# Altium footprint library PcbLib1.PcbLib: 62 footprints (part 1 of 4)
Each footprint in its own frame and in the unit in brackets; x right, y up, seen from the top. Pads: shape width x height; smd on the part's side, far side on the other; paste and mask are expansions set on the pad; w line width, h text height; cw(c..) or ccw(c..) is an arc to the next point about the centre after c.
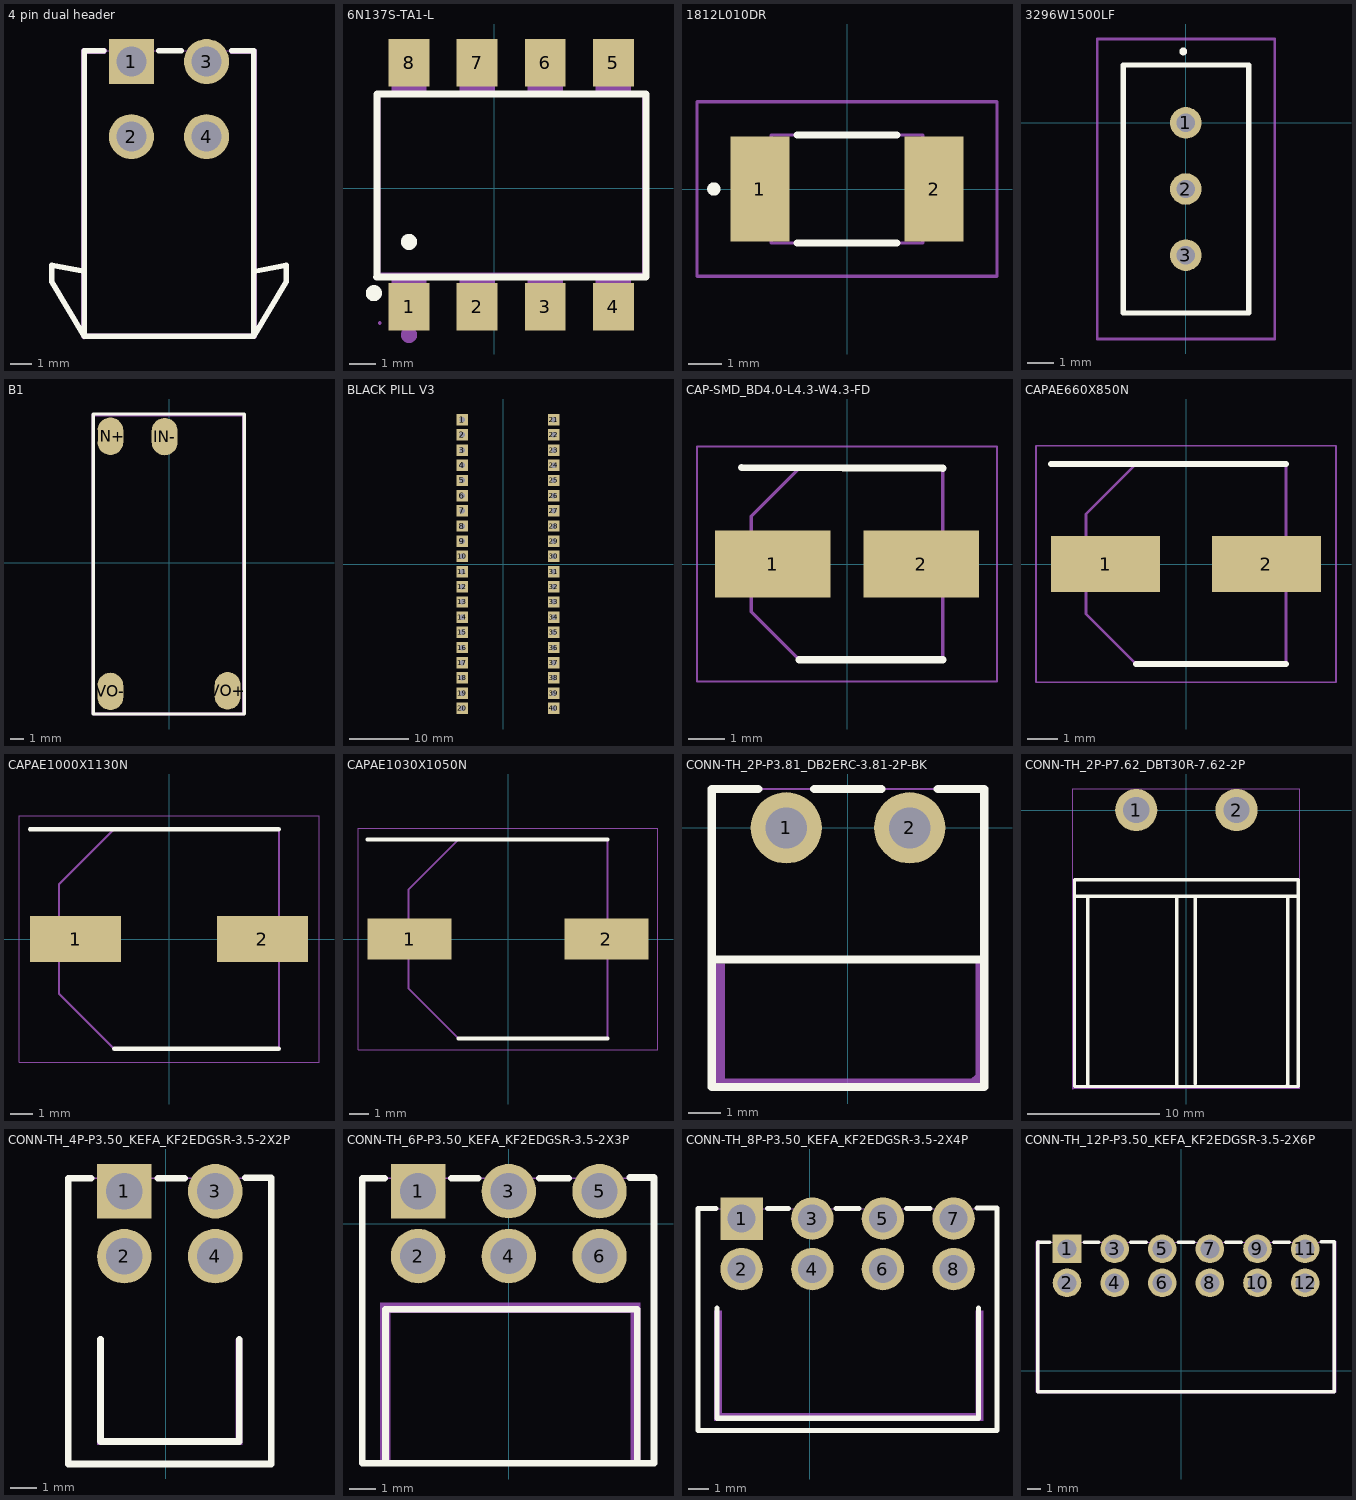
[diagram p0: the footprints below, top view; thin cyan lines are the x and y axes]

## 4 pin dual header [mm]
pads (4):
  rect 2.1x2.1 hole 1.4 paste-2539.97 mask+0.05: 1(12.728,17.118)
  round 2.1 hole 1.4 paste-2539.97 mask+0.05: 2(12.728,13.618) 3(16.228,17.118) 4(16.228,13.618)
Top Overlay:
  lines w0.254: 10.528,4.319 9.017,6.859 9.017,7.621 10.528,7.352 ; 11.447,17.618 10.528,17.618 10.528,4.318 18.428,4.318 18.428,17.527 ; 14.009,17.618 15.049,17.618 ; 17.407,17.618 18.428,17.618 ; 18.428,4.319 19.939,6.859 19.939,7.621 18.428,7.336
Mechanical 6:
  region: 11.447,17.491 10.655,17.491 10.655,4.445 18.301,4.445 18.301,17.527 18.301,17.58 18.375,17.654 18.481,17.654 18.555,17.58 18.555,17.527 18.555,4.318 18.555,4.293 18.536,4.246 18.5,4.21 18.453,4.191 18.428,4.191 10.528,4.191 10.503,4.191 10.456,4.21 10.42,4.246 10.401,4.293 10.401,4.318 10.401,17.618 10.401,17.643 10.42,17.69 10.456,17.726 10.503,17.745 10.528,17.745 11.447,17.745 11.499,17.745 11.574,17.671 11.574,17.565 11.499,17.491
  region: 17.407,17.745 18.428,17.745 18.481,17.745 18.555,17.671 18.555,17.565 18.481,17.491 18.428,17.491 17.407,17.491 17.355,17.491 17.28,17.565 17.28,17.671 17.355,17.745
Mechanical 15:
  region: 10.588,17.618 10.587,17.642 10.552,17.676 10.504,17.676 10.469,17.642 10.468,17.618 10.469,17.594 10.504,17.56 10.552,17.56 10.587,17.594
  region: 12.328,17.518 13.128,17.518 13.128,16.718 12.328,16.718
  region: 12.328,14.018 13.128,14.018 13.128,13.218 12.328,13.218
  region: 15.828,17.518 16.628,17.518 16.628,16.718 15.828,16.718
  region: 15.828,14.018 16.628,14.018 16.628,13.218 15.828,13.218
  lines w0.051: 10.528,4.318 10.528,17.618 18.428,17.618 18.428,4.318 10.528,4.318

## 6N137S-TA1-L [mm]
pads (8):
  rect 1.525x1.78 smd: 1(-3.175,-4.418) 2(-0.635,-4.418) 3(1.905,-4.418) 4(4.445,-4.418) 5(4.445,4.672) 6(1.905,4.672) 7(-0.635,4.672) 8(-3.175,4.672)
Top Overlay:
  circle w0.3: c-3.175,-2.002 r0.15
  circle w0.3: c-4.485,-3.913 r0.15
  lines w0.254: -4.385,-3.313 5.665,-3.313 5.665,3.517 4.925,3.517 -4.365,3.517 -4.375,-3.293
Mechanical 6:
  circle w0.3: c-3.175,-5.473 r0.15
Mechanical 15:
  region: -4.205,-5.023 -4.205,-4.998 -4.24,-4.963 -4.29,-4.963 -4.325,-4.998 -4.325,-5.023 -4.325,-5.048 -4.29,-5.083 -4.24,-5.083 -4.205,-5.048
  region: 3.795,3.417 3.795,4.337 5.095,4.337 5.095,3.417
  region: 3.795,4.327 3.795,5.277 5.095,5.277 5.095,4.327
  region: 1.255,3.417 1.255,4.337 2.555,4.337 2.555,3.417
  region: 1.255,4.327 1.255,5.277 2.555,5.277 2.555,4.327
  region: -1.285,3.417 -1.285,4.337 0.015,4.337 0.015,3.417
  region: -1.285,4.327 -1.285,5.277 0.015,5.277 0.015,4.327
  region: -3.825,3.417 -3.825,4.337 -2.525,4.337 -2.525,3.417
  region: -3.825,4.327 -3.825,5.277 -2.525,5.277 -2.525,4.327
  region: 3.795,-4.083 3.795,-3.163 5.095,-3.163 5.095,-4.083
  region: 3.795,-5.023 3.795,-4.073 5.095,-4.073 5.095,-5.023
  region: 1.255,-4.083 1.255,-3.163 2.555,-3.163 2.555,-4.083
  region: 1.255,-5.023 1.255,-4.073 2.555,-4.073 2.555,-5.023
  region: -1.285,-4.083 -1.285,-3.163 0.015,-3.163 0.015,-4.083
  region: -1.285,-5.023 -1.285,-4.073 0.015,-4.073 0.015,-5.023
  region: -3.825,-4.083 -3.825,-3.163 -2.525,-3.163 -2.525,-4.083
  region: -3.825,-5.023 -3.825,-4.073 -2.525,-4.073 -2.525,-5.023
  lines w0.051: -4.265,-3.173 -4.265,3.427 5.535,3.427 5.535,-3.173 -4.265,-3.173
3D body "6N137S-TA1-L.STEP": height 4.61, standoff 0.01, extent -4.205,-5.08 5.475,5.08

## 1812L010DR [mm]
pads (2):
  rect 1.78x3.15 smd: 1(-2.615,0) 2(2.615,0)
Top Overlay:
  lines w0.2: -1.5,-1.62 1.5,-1.62 ; -1.5,1.62 1.5,1.62 ; -4,-0.1 ccw(c-4,0) -4,0.1 ccw(c-4,0) -4,-0.1
Mechanical 13:
  lines w0.1: -2.275,-1.62 -2.275,1.62 2.275,1.62 2.275,-1.62 -2.275,-1.62
Mechanical 15:
  lines w0.1: -4.505,-2.62 -4.505,2.62 4.505,2.62 4.505,-2.62 -4.505,-2.62
3D body "1812L200THPR.stp": height 0.75, standoff 0, extent -2.277,-1.625 2.277,1.625

## 3296W1500LF [mm]
pads (3):
  round 1.217 hole 0.71: 1(0,0) 2(0,-2.54) 3(0,-5.08)
Top Overlay:
  lines w0.2: -0.1,2.7 cw(c-0.1,2.75) -0.1,2.8 ; -0.1,2.7 ccw(c-0.1,2.75) -0.1,2.8 ; -0.1,2.7 cw(c-0.1,2.75) -0.1,2.8 ; -2.41,-7.305 -2.41,2.225 2.42,2.225 2.42,-7.305 -2.41,-7.305
Mechanical 13:
  lines w0.1: -2.41,-7.305 -2.41,2.225 2.42,2.225 2.42,-7.305 -2.41,-7.305
Mechanical 15:
  lines w0.1: -3.41,-8.305 -3.41,3.225 3.42,3.225 3.42,-8.305 -3.41,-8.305
3D body "3296W-1-500LF.stp": height 11.9, standoff -5, extent -2.41,-7.305 2.42,2.225

## B1 [mm]
pads (4):
  oval 1.9x2.75 smd: IN+(-4.319,9.288) IN-(-0.336,9.264) VO+(4.284,-9.39) VO-(-4.323,-9.429)
Top Overlay:
  lines w0.254: -5.588,-11.087 5.488,-11.087 5.488,10.922 -5.588,10.922 -5.588,-11.087
Mechanical 1:
  lines w0.254: -5.587,-11.088 -5.587,10.87 5.469,10.87 5.469,-11.088 -5.587,-11.088
3D body "mini dc dc boost module.step": height 3.4, standoff -1, extent -5.459,-10.964 5.341,10.836

## BLACK PILL V3 [mil]
pads (40):
  rect 75x75 hole 36 paste-99999 mask+4: 1(-267.5,950) 2(-267.5,850) 3(-267.5,750) 4(-267.5,650) 5(-267.5,550) 6(-267.5,450) 7(-267.5,350) 8(-267.5,250) 9(-267.5,150) 10(-267.5,50) 11(-267.5,-50) 12(-267.5,-150) 13(-267.5,-250) 14(-267.5,-350) 15(-267.5,-450) 16(-267.5,-550) 17(-267.5,-650) 18(-267.5,-750) 19(-267.5,-850) 20(-267.5,-950) 21(332.5,950) 22(332.5,850) 23(332.5,750) 24(332.5,650) 25(332.5,550) 26(332.5,450) 27(332.5,350) 28(332.5,250) 29(332.5,150) 30(332.5,50) 31(332.5,-50) 32(332.5,-150) 33(332.5,-250) 34(332.5,-350) 35(332.5,-450) 36(332.5,-550) 37(332.5,-650) 38(332.5,-750) 39(332.5,-850) 40(332.5,-950)
3D body "Black Pill.step": height 124.41, standoff -403.94, extent -365,-1175 435,1054.92

## CAP-SMD_BD4.0-L4.3-W4.3-FD [mm]
pads (2):
  rect 3.2x1.85 smd: 1(-2.05,0) 2(2.05,0)
Top Overlay:
  lines w0.2: -2.921,2.667 2.65,2.65 ; -1.325,-2.65 2.65,-2.65
Mechanical 13:
  lines w0.1: -2.65,-1.325 -1.325,-2.65 2.65,-2.65 2.65,2.65 -1.325,2.65 -2.65,1.325 -2.65,-1.325
Mechanical 15:
  lines w0.05: -4.15,-3.25 -4.15,3.25 4.15,3.25 4.15,-3.25 -4.15,-3.25
3D body "UWT1E100MCL1GB.stp": height 5.5, standoff 0, extent -2.95,-2.75 2.95,2.75

## CAPAE660X850N [mm]
pads (2):
  rect 3.6x1.85 smd: 1(-2.65,0) 2(2.65,0)
Top Overlay:
  lines w0.2: -4.45,3.3 3.3,3.3 ; -1.65,-3.3 3.3,-3.3
Mechanical 13:
  lines w0.1: -3.3,-1.65 -3.3,1.65 -1.65,3.3 3.3,3.3 3.3,-3.3 -1.65,-3.3 -3.3,-1.65
Mechanical 15:
  lines w0.05: -4.95,-3.9 4.95,-3.9 4.95,3.9 -4.95,3.9 -4.95,-3.9
3D body "AEK0608100M100R.stp": height 8.5, standoff 0, extent -3.75,-3.4 3.75,3.4

## CAPAE1000X1130N [mm]
pads (2):
  rect 4.15x2.1 smd: 1(-4.25,0) 2(4.25,0)
Top Overlay:
  lines w0.2: -6.325,5 5,5 ; -2.5,-5 5,-5
Mechanical 13:
  lines w0.1: -5,-2.5 -5,2.5 -2.5,5 5,5 5,-5 -2.5,-5 -5,-2.5
Mechanical 15:
  lines w0.05: -6.825,-5.6 6.825,-5.6 6.825,5.6 -6.825,5.6 -6.825,-5.6
3D body "476SML100M.stp": height 11.3, standoff 0, extent -5.6,-5.1 5.6,5.1

## CAPAE1030X1050N [mm]
pads (2):
  rect 4.35x2.1 smd: 1(-5.1,0) 2(5.1,0)
Top Overlay:
  lines w0.2: -7.275,5.15 5.15,5.15 ; -2.575,-5.15 5.15,-5.15
Mechanical 13:
  lines w0.1: -5.15,-2.575 -5.15,2.575 -2.575,5.15 5.15,5.15 5.15,-5.15 -2.575,-5.15 -5.15,-2.575
Mechanical 15:
  lines w0.05: -7.775,-5.75 7.775,-5.75 7.775,5.75 -7.775,5.75 -7.775,-5.75
3D body "EDH476M100A9PAA.stp": height 10.51, standoff 0, extent -6.1,-5.25 6.1,5.25

## CONN-TH_2P-P3.81_DB2ERC-3.81-2P-BK [mm]
pads (2):
  round 2.2 hole 1.27: 1(-1.905,0) 2(1.905,0)
Top Overlay:
  lines w0.254: -4.205,-4.064 4.205,-4.064 ; -2.771,1.2 -4.205,1.2 -4.205,-8 4.205,-8 4.205,1.2 2.771,1.2 ; -1.039,1.2 1.039,1.2
Mechanical 6:
  region: 4.191,-4.064 4.191,-8.001 -4.191,-8.001 -4.191,-4.191 -3.81,-4.191 -3.81,-7.747 3.81,-7.747 3.937,-7.62 3.937,-4.064
Mechanical 15:
  region: -4.145,-8 -4.145,-8.025 -4.18,-8.06 -4.23,-8.06 -4.265,-8.025 -4.265,-8 -4.265,-7.975 -4.23,-7.94 -4.18,-7.94 -4.145,-7.975 -4.145,-8
  region: 1.505,0.4 2.305,0.4 2.305,-0.4 1.505,-0.4
  region: -2.305,0.4 -1.505,0.4 -1.505,-0.4 -2.305,-0.4
  lines w0.051: -4.205,-8 4.205,-8 4.205,1.2 -4.205,1.2 -4.205,-8

## CONN-TH_2P-P7.62_DBT30R-7.62-2P [mm]
pads (2):
  round 3.2 hole 2: 1(-3.81,0) 2(3.81,0)
Top Overlay:
  lines w0.254: -8.5,-6.554 8.5,-6.554 ; -7.486,-21 -7.486,-6.554 ; -0.735,-21 -0.735,-6.554 ; 0.668,-20.79 0.668,-6.554 ; 7.553,-21 7.687,-20.866 7.687,-20.86 7.687,-6.554 ; 8.5,-21 -8.5,-21 -8.5,-5.3 8.5,-5.3 8.5,-20.99
Mechanical 15:
  region: -2.91,0 -2.91,-0.118 -2.971,-0.347 -3.09,-0.553 -3.257,-0.72 -3.463,-0.839 -3.692,-0.9 -3.928,-0.9 -4.157,-0.839 -4.363,-0.72 -4.53,-0.553 -4.649,-0.347 -4.71,-0.118 -4.71,0 -4.71,0.118 -4.649,0.347 -4.53,0.553 -4.363,0.72 -4.157,0.839 -3.928,0.9 -3.692,0.9 -3.463,0.839 -3.257,0.72 -3.09,0.553 -2.971,0.347 -2.91,0.118
  region: 4.71,0 4.71,-0.118 4.649,-0.347 4.53,-0.553 4.363,-0.72 4.157,-0.839 3.928,-0.9 3.692,-0.9 3.463,-0.839 3.257,-0.72 3.09,-0.553 2.971,-0.347 2.91,-0.118 2.91,0 2.91,0.118 2.971,0.347 3.09,0.553 3.257,0.72 3.463,0.839 3.692,0.9 3.928,0.9 4.157,0.839 4.363,0.72 4.53,0.553 4.649,0.347 4.71,0.118
  region: -8.567,-21.127 -8.567,-21.152 -8.602,-21.187 -8.652,-21.187 -8.687,-21.152 -8.687,-21.127 -8.687,-21.102 -8.652,-21.067 -8.602,-21.067 -8.567,-21.102
  lines w0.051: -8.627,-21.127 8.627,-21.127 8.627,1.6 -8.627,1.6 -8.627,-21.127

## CONN-TH_4P-P3.50_KEFA_KF2EDGSR-3.5-2X2P [mm]
pads (4):
  rect 2.1x2.1 hole 1.4 paste-2539.97 mask+0.05: 1(-1.6,11.897)
  round 2.1 hole 1.4 paste-2539.97 mask+0.05: 2(-1.6,9.397) 3(1.9,11.897) 4(1.9,9.397)
Top Overlay:
  lines w0.254: -3.759,1.397 -3.759,12.397 -2.881,12.397 ; -3.75,1.397 4.05,1.397 4.05,12.425 3.067,12.425 ; -2.517,6.202 -2.517,2.265 2.817,2.265 2.817,6.202 ; -0.319,12.397 0.721,12.397
Mechanical 6:
  region: 2.69,6.202 2.69,2.392 -2.39,2.392 -2.39,6.202 -2.644,6.202 -2.644,2.138 2.817,2.138 2.944,2.138 2.944,6.202
Mechanical 15:
  region: -3.69,12.397 -3.69,12.372 -3.725,12.337 -3.775,12.337 -3.81,12.372 -3.81,12.397 -3.81,12.422 -3.775,12.457 -3.725,12.457 -3.69,12.422
  region: 1.5,9.797 2.3,9.797 2.3,8.997 1.5,8.997
  region: 1.5,12.297 2.3,12.297 2.3,11.497 1.5,11.497
  region: -2,9.797 -1.2,9.797 -1.2,8.997 -2,8.997
  region: -2,12.297 -1.2,12.297 -1.2,11.497 -2,11.497
  lines w0.051: -3.75,1.397 -3.75,12.397 4.05,12.397 4.05,1.397 -3.75,1.397

## CONN-TH_6P-P3.50_KEFA_KF2EDGSR-3.5-2X3P [mm]
pads (6):
  rect 2.1x2.1 hole 1.4 paste-2539.97 mask+0.05: 1(-3.5,1.25)
  round 2.1 hole 1.4 paste-2539.97 mask+0.05: 2(-3.5,-1.25) 3(0,1.25) 5(3.5,1.25) 6(3.5,-1.25)
  round 2.1 hole 1.4 copper offset 0,0 paste-2539.97 mask+0.05: 4(0,-1.25)
Top Overlay:
  lines w0.254: -5.659,-9.25 -5.659,1.75 -4.781,1.75 ; -5.65,-9.25 5.6,-9.25 5.6,1.778 4.667,1.778 ; -4.756,-9.25 -4.756,-3.302 4.953,-3.302 4.953,-9.25 ; -2.219,1.75 -1.179,1.75 ; 1.179,1.75 2.321,1.75
Mechanical 6:
  region: -4.953,-9.25 -4.953,-3.048 5.08,-3.048 5.08,-9.25 4.699,-9.25 4.699,-3.429 -4.572,-3.429 -4.572,-9.25 -4.699,-9.271
Mechanical 15:
  region: -5.59,1.75 -5.59,1.725 -5.625,1.69 -5.675,1.69 -5.71,1.725 -5.71,1.75 -5.71,1.775 -5.675,1.81 -5.625,1.81 -5.59,1.775
  region: 3.1,-0.85 3.9,-0.85 3.9,-1.65 3.1,-1.65
  region: 3.1,1.65 3.9,1.65 3.9,0.85 3.1,0.85
  region: -3.9,1.65 -3.1,1.65 -3.1,0.85 -3.9,0.85
  region: -3.9,-0.85 -3.1,-0.85 -3.1,-1.65 -3.9,-1.65
  region: -0.4,1.65 0.4,1.65 0.4,0.85 -0.4,0.85
  region: -0.4,-0.85 0.4,-0.85 0.4,-1.65 -0.4,-1.65
  lines w0.051: -5.65,-9.25 -5.65,1.75 5.65,1.75 5.65,-9.25 -5.65,-9.25

## CONN-TH_8P-P3.50_KEFA_KF2EDGSR-3.5-2X4P [mm]
pads (8):
  rect 2.1x2.1 hole 1.4 paste-2539.97 mask+0.05: 1(-3.378,16.088)
  round 2.1 hole 1.4 paste-2539.97 mask+0.05: 2(-3.378,13.588) 3(0.122,16.088) 5(3.622,16.088) 6(3.622,13.588) 7(7.122,16.088) 8(7.122,13.588)
  round 2.1 hole 1.4 copper offset 0,0 paste-2539.97 mask+0.05: 4(0.122,13.588)
Top Overlay:
  lines w0.254: -5.537,5.588 -5.537,16.588 -4.659,16.588 ; -5.528,5.588 9.272,5.588 9.272,16.616 8.289,16.616 ; -4.605,11.663 -4.605,6.202 8.349,6.202 8.349,11.663 ; -2.097,16.588 -1.057,16.588 ; 1.301,16.588 2.443,16.588 ; 4.801,16.588 5.943,16.588
Mechanical 6:
  region: 8.222,11.536 8.222,6.456 -4.351,6.456 -4.351,11.536 -4.732,11.536 -4.732,6.075 8.603,6.075 8.603,11.536
Mechanical 15:
  region: -5.468,16.588 -5.468,16.563 -5.503,16.528 -5.553,16.528 -5.588,16.563 -5.588,16.588 -5.588,16.613 -5.553,16.648 -5.503,16.648 -5.468,16.613
  region: 6.722,13.988 7.522,13.988 7.522,13.188 6.722,13.188
  region: 6.722,16.488 7.522,16.488 7.522,15.688 6.722,15.688
  region: 3.222,13.988 4.022,13.988 4.022,13.188 3.222,13.188
  region: 3.222,16.488 4.022,16.488 4.022,15.688 3.222,15.688
  region: -3.778,16.488 -2.978,16.488 -2.978,15.688 -3.778,15.688
  region: -3.778,13.988 -2.978,13.988 -2.978,13.188 -3.778,13.188
  region: -0.278,16.488 0.522,16.488 0.522,15.688 -0.278,15.688
  region: -0.278,13.988 0.522,13.988 0.522,13.188 -0.278,13.188
  lines w0.051: -5.528,5.588 -5.528,16.588 9.272,16.588 9.272,5.588 -5.528,5.588

## CONN-TH_12P-P3.50_KEFA_KF2EDGSR-3.5-2X6P [mm]
pads (12):
  rect 2.1x2.1 hole 1.4 paste-2539.97 mask+0.05: 1(-8.388,8.969)
  round 2.1 hole 1.4 paste-2539.97 mask+0.05: 2(-8.388,6.469) 3(-4.888,8.969) 5(-1.388,8.969) 6(-1.388,6.469) 7(2.112,8.969) 8(2.112,6.469) 9(5.612,8.969) 10(5.612,6.469) 11(9.112,8.969) 12(9.112,6.469)
  round 2.1 hole 1.4 copper offset 0,0 paste-2539.97 mask+0.05: 4(-4.888,6.469)
Top Overlay:
  lines w0.254: -10.547,-1.531 -10.547,9.469 -9.669,9.469 ; -10.538,-1.531 11.262,-1.531 11.262,9.497 10.279,9.497 ; -7.107,9.469 -6.067,9.469 ; -3.709,9.469 -2.567,9.469 ; -0.209,9.469 0.933,9.469 ; 3.291,9.469 4.433,9.469 ; 6.791,9.469 7.933,9.469
Mechanical 6:
  region: -10.428,9.589 -10.578,9.589 -10.668,9.499 -10.668,-1.561 -10.578,-1.651 11.302,-1.651 11.382,-1.571 11.382,9.529 11.292,9.619 11.152,9.619 11.142,9.619 11.142,-1.401 11.132,-1.411 -10.418,-1.411 -10.428,-1.401
Mechanical 15:
  region: -10.478,9.469 -10.478,9.444 -10.513,9.409 -10.563,9.409 -10.598,9.444 -10.598,9.469 -10.598,9.494 -10.563,9.529 -10.513,9.529 -10.478,9.494
  region: -5.288,6.869 -4.488,6.869 -4.488,6.069 -5.288,6.069
  region: -5.288,9.369 -4.488,9.369 -4.488,8.569 -5.288,8.569
  region: -8.788,6.869 -7.988,6.869 -7.988,6.069 -8.788,6.069
  region: -8.788,9.369 -7.988,9.369 -7.988,8.569 -8.788,8.569
  region: -1.788,9.369 -0.988,9.369 -0.988,8.569 -1.788,8.569
  region: -1.788,6.869 -0.988,6.869 -0.988,6.069 -1.788,6.069
  region: 1.712,9.369 2.512,9.369 2.512,8.569 1.712,8.569
  region: 1.712,6.869 2.512,6.869 2.512,6.069 1.712,6.069
  region: 5.212,9.369 6.012,9.369 6.012,8.569 5.212,8.569
  region: 5.212,6.869 6.012,6.869 6.012,6.069 5.212,6.069
  region: 8.712,9.369 9.512,9.369 9.512,8.569 8.712,8.569
  region: 8.712,6.869 9.512,6.869 9.512,6.069 8.712,6.069
  lines w0.051: -10.538,-1.531 -10.538,9.469 11.262,9.469 11.262,-1.531 -10.538,-1.531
